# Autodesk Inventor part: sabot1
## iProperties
Shininess: 64.0
Length Units: 11269
Angle Units: 11279
Time Units: 11290
Mass Units: 11283
Length Display Precision: 3
Angle Display Precision: 2
Compacted: True
Part Number: sabot1
Document SubType Name: Modeling
Created: 2005-02
Material: Par défaut
Designer: LEGERET Philippe
Density: 0.0
Volumn: 0.0
Area: 0.0
PropertySet Name: Model Information
Control State: 0
Master: False
Checked Out: False
Author: LEGERET Philippe
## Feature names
1. Extrusion1
2. Extrusion2
3. Chanfrein1 [Chamfer]
4. Chanfrein3 [Chamfer]
5. Chanfrein4 [Chamfer]
6. Extrusion3
7. Extrusion4
8. Extrusion5
